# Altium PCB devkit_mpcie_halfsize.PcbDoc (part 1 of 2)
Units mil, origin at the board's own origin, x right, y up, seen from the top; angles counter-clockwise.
Board outline 1185.07 x 1313.97 mil, 4 copper layers (Top Layer, Mid-Layer 1, Mid-Layer 2, Bottom Layer), stack 34.6 mil thick; 83 components, 51 nets, 256 pads, 210 vias.
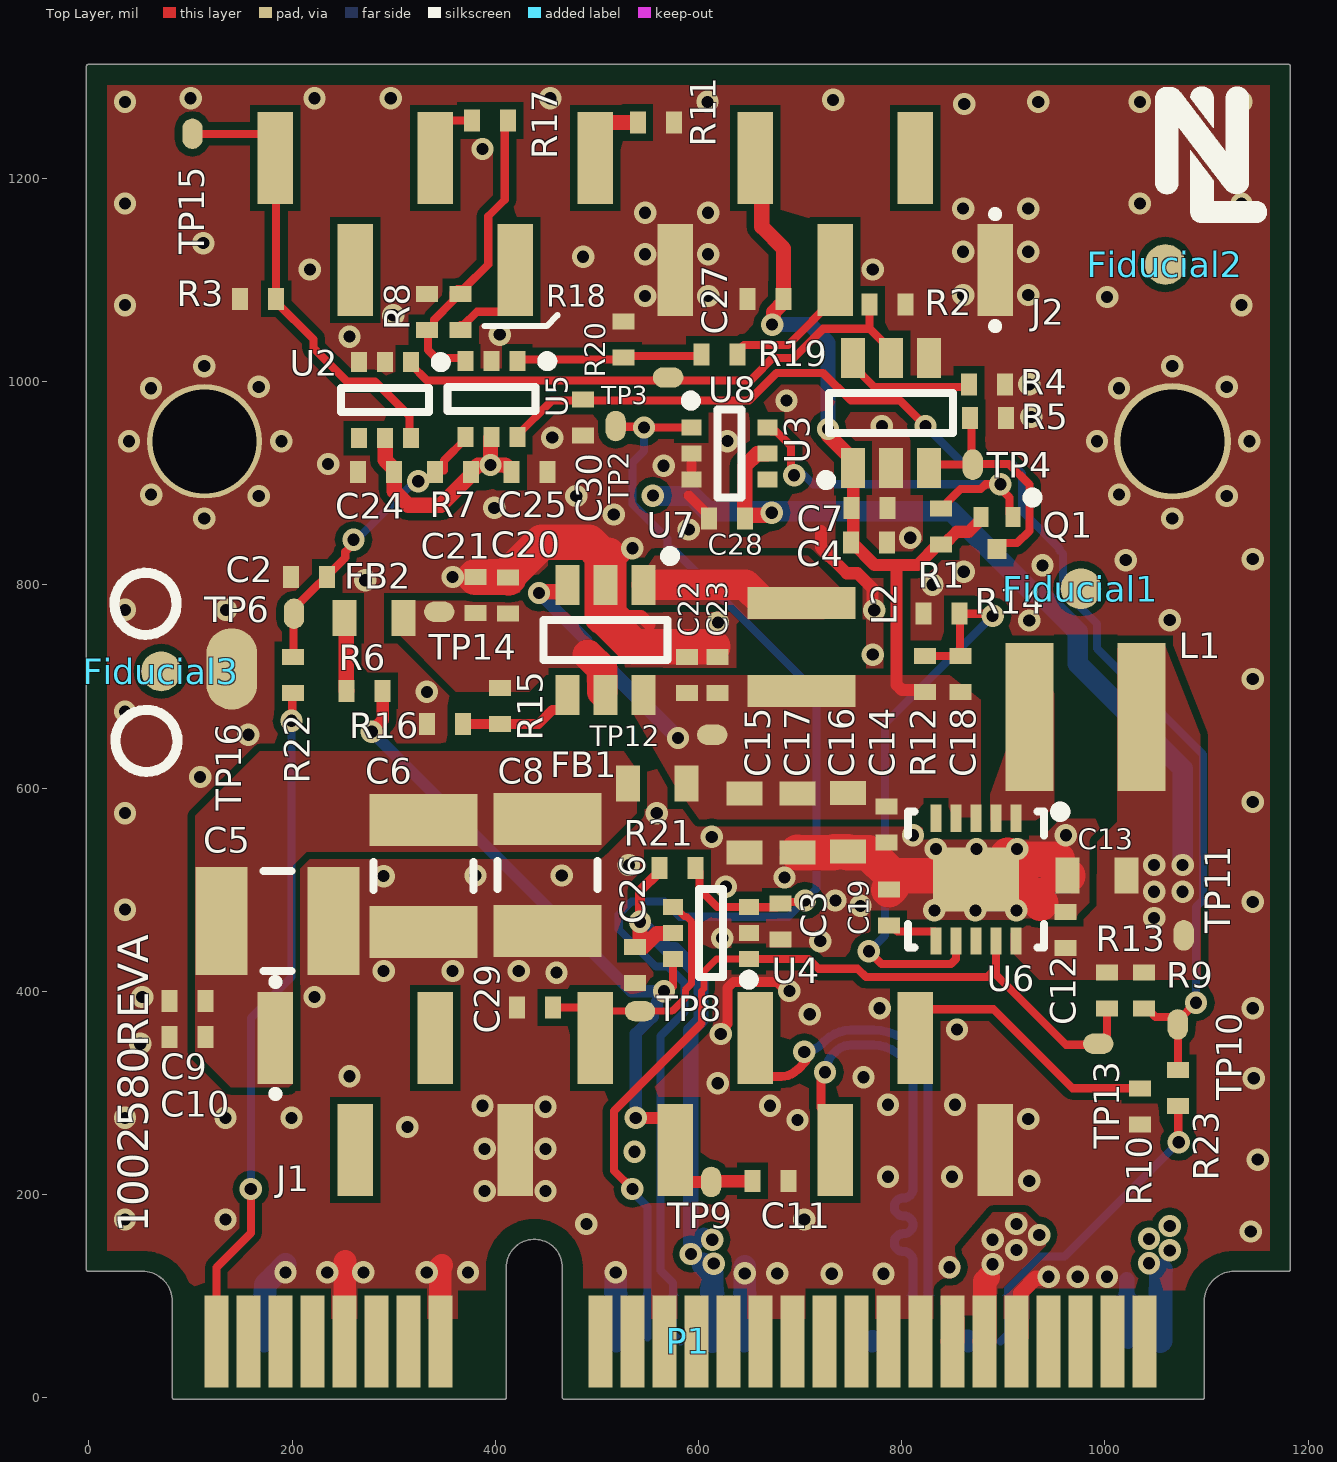
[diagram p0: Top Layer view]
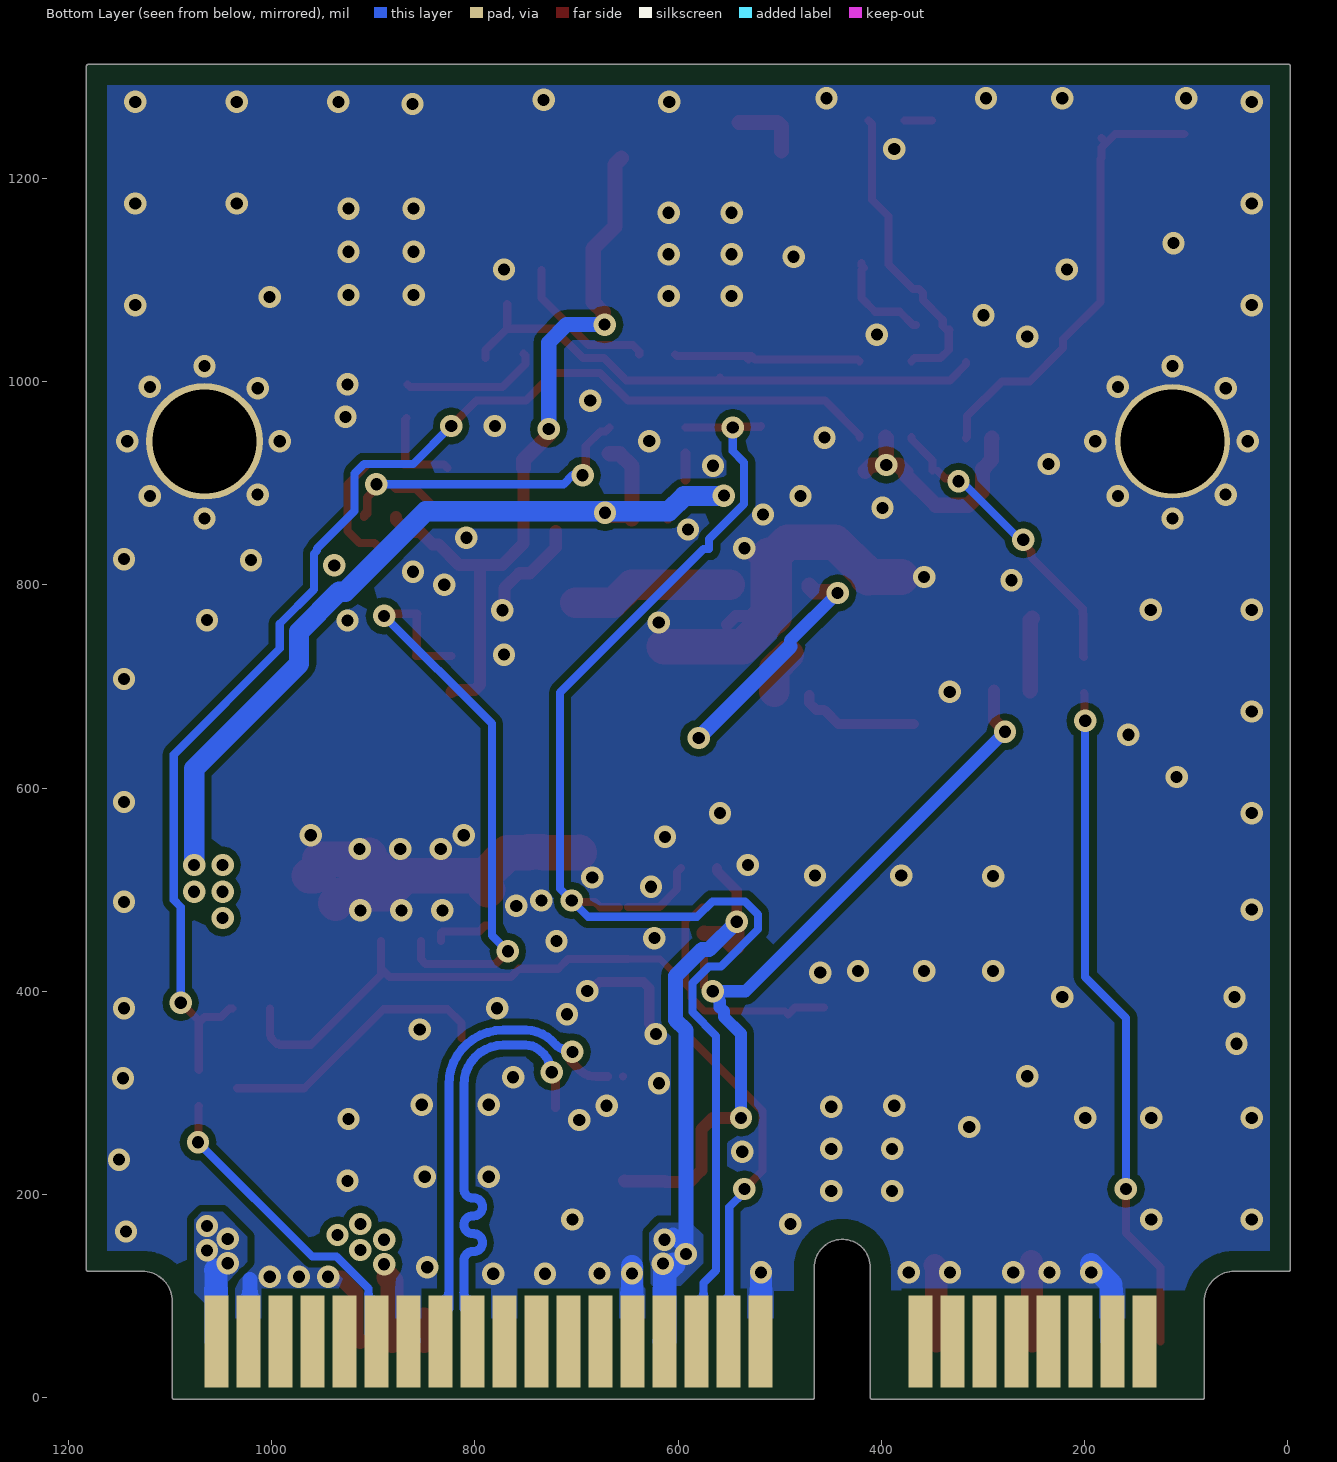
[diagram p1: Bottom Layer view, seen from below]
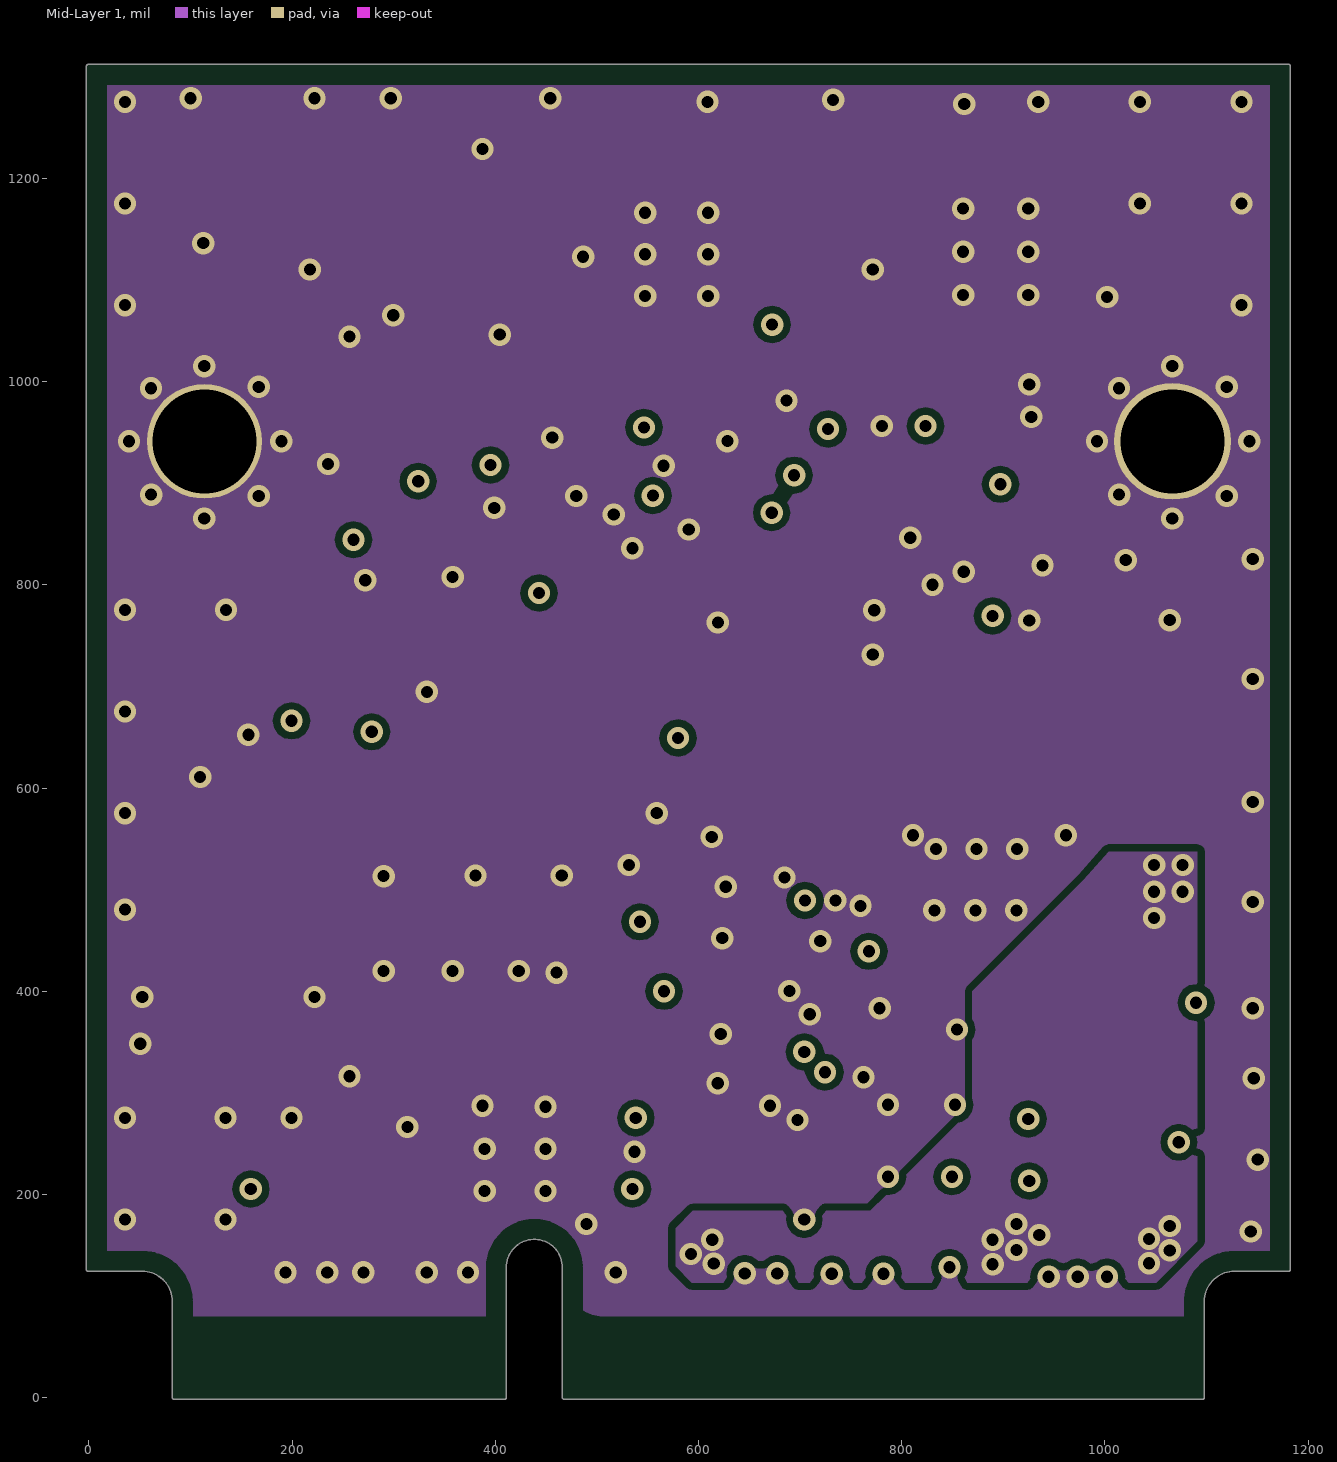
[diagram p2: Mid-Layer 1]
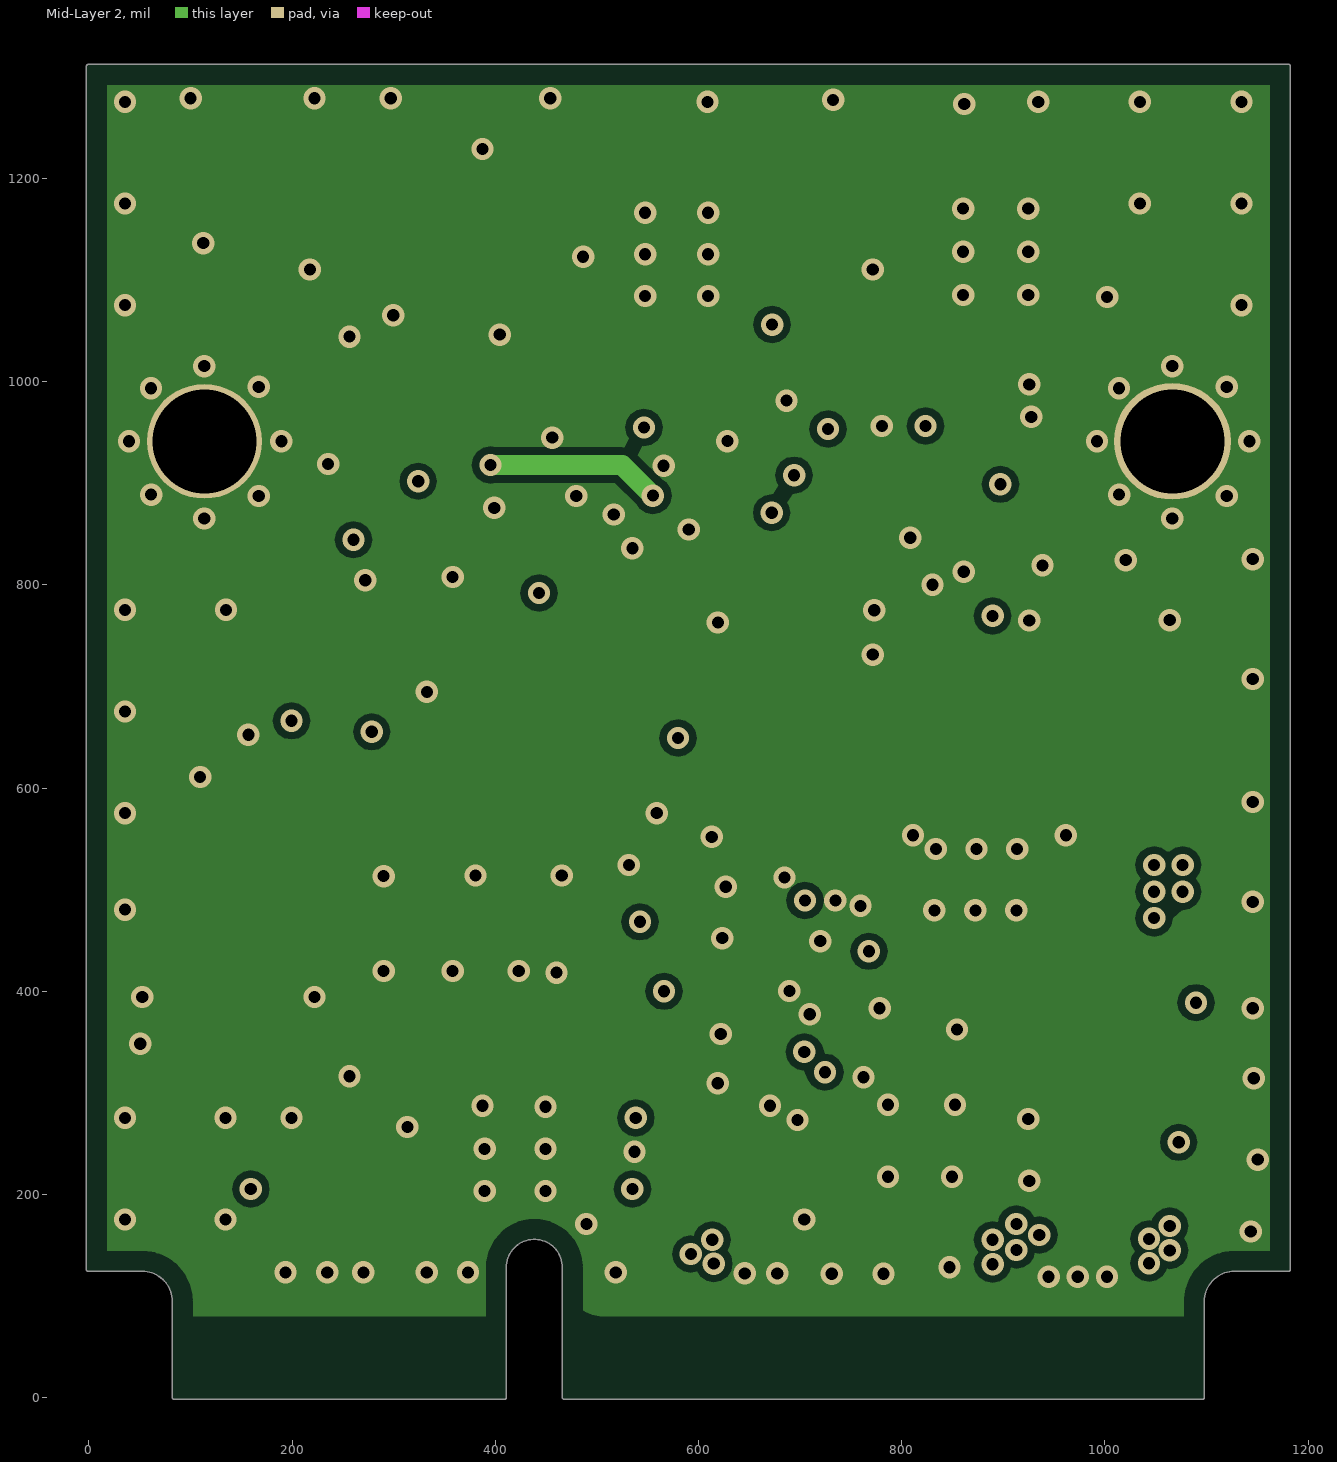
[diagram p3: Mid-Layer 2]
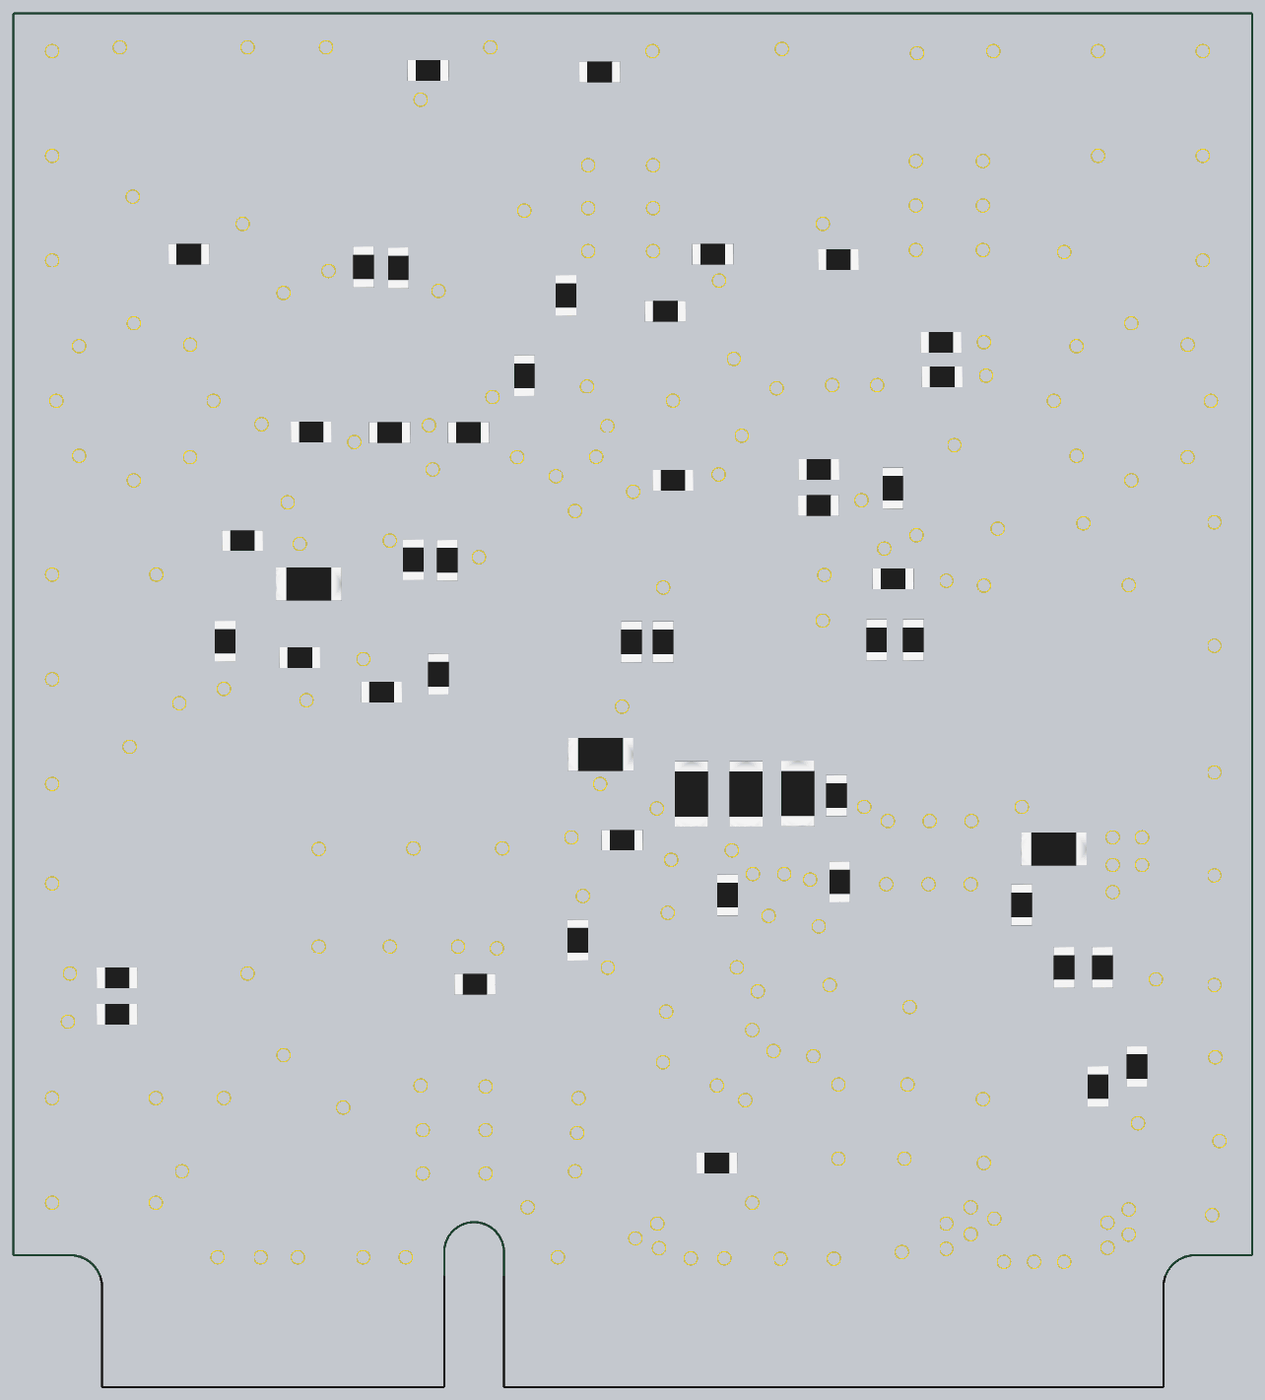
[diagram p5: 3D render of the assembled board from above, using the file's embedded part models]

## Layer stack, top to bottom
Top Solder: solder mask 1, Solder Resist, Dk 3.5
Top Layer: signal copper 0.6
Dielectric 1: dielectric 8, FR-4, Dk 4.5
Mid-Layer 1: signal copper 1.2
Dielectric2: dielectric 15, FR-4, Dk 4.5
Mid-Layer 2: signal copper 1.2
Dielectric3: dielectric 8, FR-4, Dk 4.5
Bottom Layer: signal copper 0.6
Bottom Solder: solder mask 1, Solder Resist, Dk 3.5

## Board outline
82.05,0.37 82.05,94.86 ccw(c52.54,94.86) 52.54,124.37 -0.61,124.37 cw(c-0.61,126.35) -2.6,126.35 -2.6,1310.37 cw(c-0.61,1310.37) -0.61,1312.35 1180.49,1312.35 cw(c1180.49,1310.37) 1182.47,1310.37 1182.47,126.35 cw(c1180.49,126.35) 1180.49,124.37 1127.34,124.37 ccw(c1127.34,94.86) 1097.83,94.86 1097.83,0.37 cw(c1095.84,0.37) 1095.84,-1.61 467.89,-1.61 cw(c467.89,0.37) 465.91,0.39 465.91,128.32 ccw(c438.36,128.32) 410.82,128.32 410.82,0.37 cw(c408.84,0.37) 408.84,-1.61 84.03,-1.61 cw(c84.03,0.37)

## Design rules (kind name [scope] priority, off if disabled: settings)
BoardOutlineClearance [All] p1: gap=10 ignorepadtopadclearanceinfootprint=FALSE except(0: Arc-SplitContinuation Track-SplitContinuation SMDPad-SplitContinuation THPad-SplitContinuation Via-SplitContinuation Fill-SplitContinuation Region-SplitContinuation Text-SplitContinuation; 20: Poly-OutlineEdge Poly-CavityEdge Poly-CutoutEdge Poly-SplitBarrior Poly-SplitContinuation)
Clearance "Pour Pullback" [InPoly vs OnLayer('Keep-Out Layer')] p1: gap=40 ignorepadtopadclearanceinfootprint=FALSE except(0: Arc-Hole Track-Hole SMDPad-Hole THPad-Hole Via-Hole Fill-Hole Poly-Hole Region-Hole Text-Hole)
Clearance "Polygon Clearance" [InPolygon] p2: gap=7 ignorepadtopadclearanceinfootprint=FALSE
Clearance "Trace and Space" [All] p3: gap=5 ignorepadtopadclearanceinfootprint=FALSE except(0: Arc-Hole Track-Hole SMDPad-Hole THPad-Hole Via-Hole Fill-Hole Poly-Hole Region-Hole Text-Hole)
ComponentClearance ComponentClearance_1 [Identifier='1002389_REVA_STEP'] p1: gap=0 collisioncheckmode=3 verticalgap=0 showdistances=FALSE
ComponentClearance [All] p2: gap=10 collisioncheckmode=3 verticalgap=10 showdistances=FALSE
DiffPairsRouting [All] p1: maxlimit=10 minlimit=6 mostfreqgap=6 toplayer_minwidth=7 toplayer_maxwidth=15 toplayer_prefwidth=8.8 midlayer1_minwidth=7 midlayer1_maxwidth=15 midlayer1_prefwidth=8.8 midlayer2_minwidth=7 midlayer2_maxwidth=15 midlayer2_prefwidth=8.8 bottomlayer_minwidth=7 bottomlayer_maxwidth=15 bottomlayer_prefwidth=8.8 maxuncoupledlength=500
HoleSize [All] p1: absolutevalues=TRUE maxlimit=10000 minlimit=10 maxpercent=80.000 minpercent=20.000
MinimumAnnularRing [All] p1: minimumring=5
MinimumSolderMaskSliver MinimumSolderMaskSliver_1 [InComponent('U6')] p1: minsoldermaskwidth=3
MinimumSolderMaskSliver [All] p2: minsoldermaskwidth=6
PlaneClearance [All] p1: clearance=10
PlaneConnect [All] p1: planeconnectstyle=Direct reliefexpansion=20 reliefentries=4 reliefconductorwidth=10 reliefairgap=10
PolygonConnect [All] p1: connectstyle=Direct reliefconductorwidth=10 reliefentries=4 polygonreliefangle="90 Angle" airgapwidth=10
RoutingVias [All] p1: holewidth=15 width=25 viastyle="Through Hole" minholewidth=10 minwidth=20 maxholewidth=400 maxwidth=500
SilkToSilkClearance [All] p1: silktosilkclearance=0
SilkToSolderMaskClearance [IsPad] p1: minsilkscreentomaskgap=1 clearancetoexposedcopper=TRUE
SolderMaskExpansion SolderMaskExpansion_1 [isVia] p1: expansion=-10
SolderMaskExpansion [All] p2: expansion=1
Width [All] p1: maxlimit=1000 minlimit=7 preferedwidth=8
22 further rules are at their usual default settings.

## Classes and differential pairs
component class "U_CON_PCI Express Mini_P1_52PIN": P1
component class TOP: C2 C3 C4 C5 C6 C7 C8 C9 C10 C11 C24 C25 C26 C27 C28 C29 C30 FB1 Fiducial1 Fiducial2 Fiducial3 J1 J2 PCB1 Q1 R1 R2 R3 R4 R5 R6 R7 R8 R9 R10 R11 R17 R18 R19 R20 R21 R22 R23 SCH1 TP2 TP3 TP4 TP6 TP8 TP9 TP10 TP15 TP16 U2 U3 U4 U5 U8
component class Power: C12 C13 C14 C15 C16 C17 C18 C19 C20 C21 C22 C23 FB2 L1 L2 R12 R13 R14 R15 R16 TP11 TP12 TP13 TP14 U6 U7
component class "Edge Connector": P1
differential pair SKY_USB: +SKY_USB_P -SKY_USB_N
differential pair REFCLK: +REFCLK_P -REFCLK_N
differential pair PET0: +PET0_P -PET0_N
differential pair PER0: +PER0_P -PER0_N

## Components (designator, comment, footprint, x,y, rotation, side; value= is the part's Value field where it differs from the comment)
C2 "CAPACITOR" 0402 217.21,807.8 r180 top
C3 "" 0402 680.39,469.37 r270 top
C4 "" 0402 767.37,841.37 r0 top
C5 "1001241" CAPC3225X25N_1210 185.39,469.37 r0 top
C6 "1001241" CAPC3225X25N_1210 329.36,513.37 r270 top
C7 "C, 33 pF, 50V, 5%, C0G/NP0, 0402 CER" 0402 767.71,875.62 r0 top
C8 "1001241" CAPC3225X25N_1210 451.39,514.37 r270 top
C9 "" 0402 97.39,390.37 r180 top
C10 "C, 33 pF, 50V, 5%, C0G/NP0, 0402 CER" 0402 97.39,355.37 r180 top
C11 "" 0402 670.36,213.37 r0 top
C12 "" 0402 961.53,460 r90 top
C13 "" 0603 992.14,513.91 r180 top
C14 "" 0402 784.65,564.45 r270 top
C15 "" 0603 645.39,565.62 r270 top
C16 "" 0603 747,566.37 r270 top
C17 "" 0603 697.39,565.62 r270 top
C18 "C, 18 pF, 50V, 5%, C0G/NPO, 0402 CER" 0402 857.79,712.86 r270 top
C19 "" 0402 787.39,481.84 r90 top
C20 "" 0402 412.61,789 r90 top
C21 "C, 10 uF, 10V, X5R, 20%, 0402 CER" 0402 380.4,789.62 r90 top
C22 "" 0402 588.66,711.01 r90 top
C23 "C, 10 uF, 10V, X5R, 20%, 0402 CER" 0402 618.89,711.01 r90 top
C24 "" 0402 282.85,911.46 r180 top
C25 "" 0402 433.15,910.93 r0 top
C26 "" 0402 537.39,426.22 r270 top
C27 "" 0402 666.39,1081.37 r180 top
C28 "" 0402 628.36,865.37 r180 top
C29 "CAPACITOR" 0402 439.29,384.11 r180 top
C30 "CAPACITOR" 0402 486.32,965.37 r270 top
FB1 "PE-0603PFB121ST" 0603 559.29,604.46 r180 top
FB2 "PE-0603PFB121ST" 0603 280.43,767.22 r180 top
Fiducial1 "Fiducial 1mm" "Fiducial 1mm"#1 976.39,796.3 r90 top
Fiducial2 "Fiducial 1mm" "Fiducial 1mm"#1 1059.39,1115.37 r90 top
Fiducial3 "Fiducial 1mm" "Fiducial 1mm"#2 71,715 r90 top
J1 "1000865" NPPN101BFLC-RC 183.44,354.08 r90 top locked
J2 "1000865" NPPN101BFLC-RC 891.93,1109.91 r270 top locked
L1 "INDUCTOR" MDWK4040 980.92,670 r180 top
L2 "INDUCTOR" NRS3015 701.22,739 r90 top
P1 "PCIeMini-CN-2S-M-R52" PCIeMini-GF-2D-800-1K-S52 589.94,55.49 r0 top locked
Q1 "MOSFET_P" SOT-723 893.58,851 r270 top
R1 "R, 10K, 1%, 1/16W,  0402" 0402 838.39,857.82 r270 top
R2 "R, 10K, 1%, 1/16W,  0402" 0402 786.39,1076.37 r180 top
R3 "RESISTOR" 0402 166.05,1081.35 r0 top
R4 "R, 10K, 1%, 1/16W,  0402" 0402 884.39,997.37 r180 top
R5 "R, 10K, 1%, 1/16W,  0402" 0402 885.39,964.37 r180 top
R6 "R, 1K, 1%, 1/16W, 0402" 0402 271.87,695.94 r180 top
R7 "R, 10K, 1%, 1/16W,  0402" 0402 357.87,910.93 r0 top
R8 "R, 10K, 1%, 1/16W,  0402" 0402 332.61,1069.29 r270 top
R9 "R, 10K, 1%, 1/16W,  0402" 0402 1038.76,400.23 r90 top
R10 "R, 1K, 1%, 1/16W, 0402" 0402 1034.39,286.37 r90 top
R11 "R, 1K, 1%, 1/16W, 0402" 0402 558.39,1255.37 r180 top
R12 "RESISTOR" 0402 822.82,712.86 r270 top
R13 "R, 100K, 1%, 1/16W,  0402" 0402 1002,400.23 r90 top
R14 "R, 100K, 1%, 1/16W,  0402" 0402 838.54,771.51 r0 top
R15 "R, 1M, 1%, 1/16W, 0402" 0402 404.48,680.31 r90 top
R16 "RESISTOR" 0402 350,663 r0 top
R17 "0" 0402 394.44,1257 r0 top
R18 "0" 0402 366,1068.37 r90 top
R19 "0" 0402 621,1027 r180 top
R20 "R, 10K, 1%, 1/16W,  0402" 0402 526,1042 r270 top
R21 "R, 10K, 1%, 1/16W,  0402" 0402 579.81,521.42 r180 top
R22 "0" 0402 200.54,711.75 r270 top
R23 "0" 0402 1071.62,305.37 r270 top
TP2 "Test Point 1mm" "Test_Point 1mm"#1 515.56,956.37 r90 top
TP3 "Test Point 1mm" "Test_Point 1mm"#2 558.81,993.56 r90 top
TP4 "Test Point 1mm" "Test_Point 1mm"#3 869.89,918.37 r270 top
TP6 "Test Point 1mm" "Test_Point 1mm"#3 201.82,771.66 r90 top
TP8 "Test Point 1mm" "Test_Point 1mm"#4 542.33,380.44 r90 top
TP9 "Test Point 1mm" "Test_Point 1mm"#3 612.39,212.37 r90 top
TP10 "Test Point 1mm" "Test_Point 1mm"#3 1071.62,367.37 r90 top
TP11 "Test Point 1mm" "Test_Point 1mm"#3 1077.5,455.03 r270 top
TP12 "Test Point 1mm" "Test_Point 1mm"#3 613.39,652.48 r180 top
TP13 "Test Point 1mm" "Test_Point 1mm"#3 993.39,348.37 r180 top
TP14 "Test Point 1mm" "Test_Point 1mm"#3 344.74,773.51 r180 top
TP15 "Test Point 1mm" "Test_Point 1mm"#3 101.83,1243.96 r90 top
TP16 "Test Point 1mm" "Test_Point 1mm"#5 140.54,717.25 r90 top
U2 "NL27WZ06DFT2G" SOT65P210X110-6N 291.14,981.78 r270 top
U3 "TPL5111" SOT95P280X110-6N 789.54,969.24 r90 top
U4 "NL27WZ07DFT2G" SOT65P210X110-6N 612.07,457.37 r180 top
U5 "NL27WZ06DFT2G" SOT65P210X110-6N 395.98,982.77 r270 top
U6 "TPS61230DRCR" PSON50P300X100_HS-11N 872.94,509.82 r270 top
U7 "TLV61220" SOT95P280X110-6N 508.37,745.81 r270 top
U8 "NL27WZ07DFT2G" SOT65P210X110-6N 630.32,929.37 r0 top

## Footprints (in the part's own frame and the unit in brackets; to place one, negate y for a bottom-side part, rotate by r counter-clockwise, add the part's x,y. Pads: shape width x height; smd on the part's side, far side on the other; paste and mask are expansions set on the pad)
0402 [mm]
  rect 0.4x0.55 smd: 1(-0.438,0.004) 2(0.462,0.004)
  body extent -0.5,-0.25 0.5,0.25, height 0.3
0603 [mm]
  rect 0.6x0.9 smd: 1(-0.737,0) 2(0.737,0)
  body extent -0.8,-0.38 0.8,0.42, height 0.45
CAPC3225X25N_1210 [mm] "Chip Capacitor, 2-Leads, 1210"
  rect 1.3x2.7 smd: 1(-1.4,0) 2(1.4,0)
  silkscreen extent -0.35,-1.25 0.35,1.25, body extent -1.7,-1.35 1.7,1.35, height 2.5
"Fiducial 1mm"#1 [mil]
  round 40 smd paste-19.68: Fiducial(0,0)
"Fiducial 1mm"#2 [mil]
  round 39.37 smd paste-19.68 mask+0: Fiducial(0,0)
MDWK4040 [mm] "Precision Wire Wound Inductor, 2-Leads, Body 4.00x4.00mm, IPC Medium Density"
  rect 1.2x3.7 smd: 1(-1.4,0) 2(1.4,0)
  body extent -2.1,-2.1 2.1,2.1, height 2
NPPN101BFLC-RC [mm] "Skywire Footprint with surfacemount pads"
  rect 2.29x0.89 smd: 1(0,0) 2(-2.8,-2) 3(0,-4) 4(-2.8,-6) 5(0,-8) 6(-2.8,-10) 7(0,-12) 8(-2.8,-14) 9(0,-16) 10(-2.8,-18)
  silkscreen extent -1.43,-0.03 1.43,0.03, body extent -3.54,-19.24 0.91,1.26, height 4.5
NRS3015 [mm] "Molded Inductor, 2-Leads, Body 3.00x3.00mm, IPC Medium Density"
  rect 0.8x2.7 smd: 1(-1.1,0) 2(1.1,0)
  body extent -1.55,-1.55 1.55,1.55, height 1.5
PCIeMini-GF-2D-800-1K-S52 [mm] "Golden finger, PCIeMini, Dual, Staggered, Pitch 0.8mm, 52-Position"
  rect 0.6x2.3 smd paste-0.9: 1(-11.8,0) 3(-11,0) 5(-10.2,0) 7(-9.4,0) 9(-8.6,0) 11(-7.8,0) 13(-7,0) 15(-6.2,0) 17(-2.2,0) 19(-1.4,0) 21(-0.6,0) 23(0.2,0) 25(1,0) 27(1.8,0) 29(2.6,0) 31(3.4,0) 33(4.2,0) 35(5,0) 37(5.8,0) 39(6.6,0) 41(7.4,0) 43(8.2,0) 45(9,0) 47(9.8,0) 49(10.6,0) 51(11.4,0)
  rect 0.6x2.3 smd far side paste-0.9: 2(-11.4,0) 4(-10.6,0) 6(-9.8,0) 8(-9,0) 10(-8.2,0) 12(-7.4,0) 14(-6.6,0) 16(-5.8,0) 18(-1.8,0) 20(-1,0) 22(-0.2,0) 24(0.6,0) 26(1.4,0) 28(2.2,0) 30(3,0) 32(3.8,0) 34(4.6,0) 36(5.4,0) 38(6.2,0) 40(7,0) 42(7.8,0) 44(8.6,0) 46(9.4,0) 48(10.2,0) 50(11,0) 52(11.8,0)
PSON50P300X100_HS-11N [mm] "PSON, 10-Leads, Body 3.00x3.00mm, Pitch 0.50mm, Thermal Pad 2.15x1.60mm, IPC Medium Density"
  rect 0.685x0.28 smd mask+0.07: 1(-1.532,1) 2(-1.532,0.5) 3(-1.532,0) 4(-1.532,-0.5) 5(-1.532,-1) 6(1.533,-1) 7(1.533,-0.5) 8(1.533,0) 9(1.533,0.5) 10(1.533,1)
  rect 1.6x2.15 smd paste-0.8 mask+0: 11(0,0)
  silkscreen extent -1.75,-1.7 1.7,2.09, body extent -1.55,-1.55 1.55,1.55, height 1
SOT65P210X110-6N [mm] "SOT23, 6-Leads, Body 2.00x2.10mm, Pitch 0.65mm, IPC Medium Density"
  rect 0.5x0.4 smd: 1(-0.95,0.65) 2(-0.95,0) 3(-0.95,-0.65) 4(0.95,-0.65) 5(0.95,0) 6(0.95,0.65)
  silkscreen extent -1.07,-1.1 0.3,1.53, body extent -0.67,-1.1 0.67,1.1, height 1.1
SOT95P280X110-6N [mm] "SOT23, 6-Leads, Body 2.90x2.80mm, Pitch 0.95mm, IPC Medium Density"
  rect 1x0.6 smd: 1(-1.375,0.95) 2(-1.375,0) 3(-1.375,-0.95) 4(1.375,-0.95) 5(1.375,0) 6(1.375,0.95)
  silkscreen extent -1.8,-1.55 0.5,1.75, body extent -0.88,-1.52 0.87,1.53, height 1.1
SOT-723 [mm]
  rect 0.5x0.37 smd: 1(-0.4,0.4) 2(-0.4,-0.4)
  rect 0.5x0.47 smd: 3(0.4,0)
  silkscreen extent -1.01,0.76 -0.76,1.01, body extent -0.45,-0.65 0.45,0.65, height 0.55
"Test_Point 1mm"#1 [mil]
  oval 30x20 smd paste-19.68 mask+0: 1(0,-2.83)
"Test_Point 1mm"#2 [mil]
  oval 20x30 smd paste-19.68 mask+0: 1(10.63,-11.19)
"Test_Point 1mm"#3 [mil]
  oval 30x20 smd paste-19.68 mask+0: 1(0,0)
"Test_Point 1mm"#4 [mil]
  oval 20x30 smd paste-19.68 mask+0: 1(0,0)
"Test_Point 1mm"#5 [mil]
  oval 80x50 smd paste-25 mask+0: 1(0,0)

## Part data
C2 C29 C30: library part 1000740, "Capacitor, 0.01 uF, 25V, 5%, X7R, 0402", Capacitance=0.01uF
C3 C4 C9 C11 C12 C14 C19 C20 C22 C24 C25 C26 C27 C28: library part 1000742, "Capacitor, 0.1 uF, 16V, 10%, X7R, 0402", Capacitance=0.10µF, Capacitor_Type=Ceramic, Manufacturer1=Kemet, Manufacturer2="Samsung Electro-Mechanics America, Inc", Manufacturer_Part_Number1=C0402C104K4RALTU, Manufacturer_Part_Number2=CL05B104KO5NNNC, Operating_Temperature="-55°C ~ 125°C", Package_Case="0402 (1005 Metric)", Temperature_Coefficient=X7R, Tolerance=±10%, Voltage_Rating=16V
C5 C6 C8: "Capacitor. 100uF, 10V, 20%, X5R, 1210", Capacitance=100uF, Capacitor_Type=Ceramic, Manufacturer1="Taiyo Yuden", Manufacturer_Part_Number1=LMK325BJ107MM-T, Operating_Temperature="-55C ~ +85C", Package_Case="1210 (3225 Metric)", Temperature_Coefficient=X5R, Tolerance="+/- 20%", Voltage_Rating=10V
C7 C10: library part 1000750, "Capacitor, 33 pF, 50V, 5%, C0G/NP0, 0402", Capacitance=33pF, Capacitor_Type=Ceramic, Manufacturer1=Kemet, Manufacturer_Part_Number1=C0402C330J5GACTU, Manufacturer_Part_Number2=C0402C330J5GACAUTO, Operating_Temperature="-55°C ~ 125°C", Package_Case="0402 (1005 Metric)", Temperature_Coefficient="C0G, NP0", Tolerance=±5%, Voltage_Rating=50V
C13 C15 C16 C17: library part 1000932, "Capacitor, 22 uF, 25V, 20%, X5R, 0603", Capacitance=22µF, Capacitor_Type=Ceramic, Manufacturer1="TDK Corporation", Manufacturer_Part_Number1=C1608X5R1A226M080AC, Operating_Temperature="-55°C ~ 85°C", Package_Case="0603 (1608 Metric)", Temperature_Coefficient=X5R, Tolerance=±20%, Voltage_Rating=10V
C18: library part 1000748, "Capacitor, 18 pF, 50V, 5%, C0G/NPO, 0402", Capacitance=18pF, Capacitor_Type=Ceramic, Manufacturer1="Samsung Electro-Mechanics America, Inc", Manufacturer_Part_Number1=CL05C180JB5NNNC, Operating_Temperature="-55°C ~ 125°C", Package_Case="0402 (1005 Metric)", Temperature_Coefficient="C0G, NP0", Tolerance=±5%, Voltage_Rating=50V
C21 C23: library part 1000737, "Capacitor, 10 uF, 10V, 20%, X5R, 0402", Capacitance=10µF, Capacitor_Type=Ceramic, Manufacturer1="Venkel LTD.", Manufacturer2="Samsung Electro-Mechanics America, Inc", Manufacturer_Part_Number1=C0402X5R100-106MNP, Manufacturer_Part_Number2=CL05A106MP8NUB8, Operating_Temperature="-55°C ~ 85°C", Package_Case="0402 (1005 Metric)", Temperature_Coefficient=X5R, Tolerance=±20%, Voltage_Rating=10V
FB1 FB2: library part 1000716, "Ferrite Bead, 120 ohm @100mHz, 2A, 50mOHM-DC, 0603", Manufacturer1="Murata Electronics North America", Manufacturer_Part_Number1=BLM18PG121SZ1D, Manufacturer_Part_Number2=BLM18PG121SH1D, Package_Case="0603 (1608 Metric)", Resistance_at_Frequency="120 @ 100MHz", Resistance_DC="50 mOhm"
Fiducial1 Fiducial2 Fiducial3: library part Fiducial
J1 J2: "Connector, Female, 2.00mm, 10x1, SMD, Left Oriented", Color=Black, Current_Rating=2A, Manufacturer1="Sullins Connector Solutions", Manufacturer_Part_Number1=NPPN101BFLC-RC, Operating_Temperature="-40°C ~ 105°C", Voltage_Rating=150V
L1: library part 1002223, "Inductor, 1 uH, 5.1A, 20%, 27 mOhm, Shielded, 4.00x4.00x2.00mm", Current_Rating=5.1A, Current_Saturation=7A, DC_Resistance="27 mOhm", Inductance="1.0 uH", Inductor_Type=Wirewound, Manufacturer1="Taiyo Yuden", Manufacturer_Part_Number1=MDWK4040T1R0MM, Operating_Temperature="-40C to +125C", Tolerance=20%
L2: library part 1002127, "Inductor, 4.7 uH, 1.04 A, 20%, 144 mOHM, Shielded, 3X3mm", Current_Rating=1.04A, Current_Saturation=1.02A, Inductance="4.7 uH", Inductor_Type=Wirewound, Manufacturer1="Taiyo Yuden", Manufacturer_Part_Number1=NRS3015T4R7MNGHV, Operating_Temperature="-40C to +125C", Package_Case=NR3015, Tolerance=20%
P1: library part CMP-0001-00067-2, "Golden finger, PCIeMini, Dual, Staggered, Pitch 0.8mm, 52-Position", Package Reference=PCIeMini-GF-2D-800-1K-S52, Package Version="rev1.2, Oct-2007"
Q1: library part 1001881, "Transistor, MOSFET, P-CH, 20V, 0.100A, SOT-723", Current_Continuous_Drain_at_25_deg_C="0.100 A", Drain_to_Source_Voltage=20V, Manufacturer1="Rohm Semiconductor", Manufacturer_Part_Number1=RZM001P02T2L, Operating_Temperature="-55°C ~ 150°C", Package_Case=SOT-723
R1 R2 R4 R5 R7 R8 R9 R20 R21: library part 1000795, "Resistor, 10K, 1%, 1/16W, 0402", Manufacturer1="Bourns Inc", Manufacturer_Part_Number1=CR0402-FX-1002GLF, Manufacturer_Part_Number2=CR0402-FX-1002GAS, Operating_Temperature="-55°C ~ 155°C", Power="0.063W, 1/16W", Resistance_Ohms=10k, Resistor_Package="0402 (1005 Metric)", Temperature_Coefficient=±100ppm/°C, Tolerance=±1%
R3: library part 1001865, "Resistor, 0, 1/16W, 0402", Manufacturer1="Bourns Inc", Manufacturer2="Samsung Electro-Mechanics America, Inc", Manufacturer_Part_Number1=CR0402-J/-000GLF, Manufacturer_Part_Number2=RCS1005J000CS, Operating_Temperature="-55C ~ 155C", Power=1/16W, Resistance_Ohms=0, Resistor_Package="0402 (1005 Metric)"
R6 R10 R11: library part 1000794, "Resistor, 1K, 1%, 1/16W, 0402", Manufacturer1="Bourns Inc", Manufacturer2="Samsung Electro-Mechanics America, Inc", Manufacturer_Part_Number1=CR0402-FX-1001GLF, Manufacturer_Part_Number2=RC1005F102CS, Operating_Temperature="-55°C ~ 155°C", Power="0.063W, 1/16W", Resistance_Ohms=1k, Resistor_Package="0402 (1005 Metric)", Temperature_Coefficient=±100ppm/°C, Tolerance=±1%
R12: library part 1002126, "Resistor, 300K, 1%, 1/16W, 0402", Manufacturer1="Stackpole Electronics Inc", Manufacturer2=Yageo, Manufacturer_Part_Number1=RMCF0402FT300k, Manufacturer_Part_Number2=RC0402FR-07300KL, Operating_Temperature="-55C to 155C", Power=1/16W, Resistance_Ohms=300k, Resistor_Package="0402 (1005 Metric)", Temperature_Coefficient=±100ppm/°C, Tolerance=1%
R13 R14: library part 1000796, "Resistor, 100K, 1%, 1/16W, 0402", Manufacturer1="Bourns Inc", Manufacturer2="Samsung Electro-Mechanics America, Inc", Manufacturer_Part_Number1=CR0402-FX-1003GLF, Manufacturer_Part_Number2=RC1005F104CS, Operating_Temperature="-55°C ~ 155°C", Power="0.063W, 1/16W", Resistance_Ohms=100k, Resistor_Package="0402 (1005 Metric)", Temperature_Coefficient=±100ppm/°C, Tolerance=±1%
R15: library part 1000797, "Resistor, 1M, 1%, 1/16W, 0402", Manufacturer1="Bourns Inc", Manufacturer2="Samsung Electro-Mechanics America, Inc", Manufacturer_Part_Number1=CR0402-FX-1004GLF, Manufacturer_Part_Number2=RC1005F105CS, Operating_Temperature="-55°C ~ 155°C", Power="0.063W, 1/16W", Resistance_Ohms=1M, Resistor_Package="0402 (1005 Metric)", Temperature_Coefficient=±100ppm/°C, Tolerance=±1%
R16: library part 1002128, "Resistor, 110K, 1%, 1/16W, 0402", Manufacturer1=Yageo, Manufacturer_Part_Number1=RC0402FR-07110KL, Operating_Temperature="-55C to +125C", Power=1/16W, Resistance_Ohms=110K, Resistor_Package="0402 (1005 Metric)", Temperature_Coefficient=±100ppm/°C, Tolerance=1%
R17 R18 R19 R22 R23: library part 1000574, "Resistor, 0, 1/10W, 0402", Manufacturer1="Panasonic Electronic Components", Manufacturer_Part_Number1=ERJ-2GE0R00X, Operating_Temperature="-55°C ~ 155°C", Power="0.1W, 1/10W", Resistor_Package="0402 (1005 Metric)", Temperature_Coefficient=-, Tolerance=Jumper
TP2 TP3 TP4 TP6 TP8 TP9 TP10 TP11 TP12 TP13 TP14 TP15 TP16: library part TP_1mm, "TEST POINT, SMD 1mm"
U2 U5: library part 1000524, "IC, Inverter, Dual, Open Drain,1.65-5.5V, SC88", Manufacturer1="ON Semiconductor", Operating_Temperature="-55°C ~ 125°C", Package_Case="6-TSSOP, SC-88, SOT-363", Voltage_Supply_Max=5.5V, Voltage_Supply_Min=1.65V, Voltage_Supply_Typical=-
U3: library part 1002129, "IC, Timer, 0.1-7200s, 1%, 1.8V-5.5V, TSOT-23-6", Manufacturer1="Texas Instruments", Manufacturer_Part_Number1=TPL5111DDCR, Operating_Temperature="-40C to +105C", Package_Case=TSOT-23-6, Voltage_Supply_Max=5.5V, Voltage_Supply_Min=1.8V, Voltage_Supply_Typical=3.3V
U4 U8: library part 1001575, "IC, Buffer, Dual, Open Drain,1.65-5.5V, SC88", Manufacturer1="ON Semiconductor", Operating_Temperature="-55°C ~ 125°C", Package_Case="6-TSSOP, SC-88, SOT-363", Voltage_Supply_Max=5.5V, Voltage_Supply_Min=1.65V, Voltage_Supply_Typical=-
U6: library part 1001034, "IC, Boost, ADJ, 2.5V-5.5V, 2.1A, VSON", Manufacturer1="Texas Instruments", Operating_Temperature="-40°C ~ 125°C", Package_Case="10-VFDFN Exposed Pad", Voltage_Supply_Typical=-
U7: library part 1002116, "IC, BOOST, ADJ, 1.8V-5.5V, 0.22A, SOT-23-6", Manufacturer1="Texas Instruments", Manufacturer_Part_Number1=TLV61220DBVR, Operating_Temperature="-40C to +85C", Package_Case=SOT-23-6, Voltage_Supply_Max=5.5V, Voltage_Supply_Min=0.7V, Voltage_Supply_Typical=3.3

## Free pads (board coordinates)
  oval 20x60 on Mech15: 1(183.44,354.08) 2(891.93,1116.91)
  round 200 on Top Solder: 3(1066.32,941.32) 4(113.56,941.32)
  round 113 hole 102.36: MH1(113.56,941.32)
  round 115 hole 102.36: MH2(1066.32,941.32)

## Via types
v1: diameter 22, hole 12, Top Layer to Bottom Layer, 210 vias

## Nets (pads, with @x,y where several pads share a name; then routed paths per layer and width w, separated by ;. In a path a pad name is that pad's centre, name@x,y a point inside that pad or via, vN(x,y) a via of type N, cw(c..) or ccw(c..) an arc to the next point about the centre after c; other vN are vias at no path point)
CLKREQ#: P1.7
COEX1: P1.3
COEX2: P1.5
GND: C2.2 C3.2 C4.2 C5.2 C6.2 C7.2 C8.2 C9.2 C10.2 C11.2 C12.2 C13.2 C14.2 C15.2 C16.2 C17.2 C19.2 C20.2 C21.2 C22.2 C23.2 C24.2 C25.2 C26.2 C27.2 C28.2 C29.2 C30.2 J1.4 J1.10 J2.1 J2.5 P1.4 P1.9 P1.15 P1.18 P1.21 P1.26 P1.27 P1.29 P1.34 P1.35 P1.37 P1.40 P1.43 P1.50 pad.MH1 pad.MH2 R2.1 R3.1 R4.1 R5.1 R8.1 R10.1 R11.1 R14.1 R16.1 R20.1 TP16.1 U2.2 U2.3 U3.2 U3.4 U4.2 U5.2 U6.11 U7.2 U8.2 U8.3 | length 1658.8
  Top Layer w10: 590.35,888 610.19,868.17 C28.2@610.19,865.22 ; U8.3@592.91,903.78 U8.2@592.91,929.37 ; v1(621.88,358) 621.88,361.25 628.36,367.73 628.36,403.3 634.22,409.16 677.54,409.16 686.46,400.23 v1(689.4,400.23)
  Top Layer w12: U7.2@511,810.45 522.96,822.41 ; v1@534.82,836.05 522.96,824.19 522.96,822.41 ; 551.78,760.86 543.38,769.26 529.4,769.26 522.96,775.7 522.96,822.41 ; 720.5,852.93 720.5,836.88 745.84,811.54 756.44,811.54 771.04,796.95 771.04,776.91 v1(772.95,774.99)
  Top Layer w15: P1.43@912.77,55.49 917.09,59.8 917.09,103.07 931.65,117.64 943.17,117.64 v1(944.51,118.97)
  Top Layer w22: P1.9@251.36,55.49 251.78,55.91 251.78,133.76 252.39,134.37 ; P1.15@345.84,55.49 345.84,128.83 347.39,130.37
  Top Layer w35: C21.2@380.25,807.8 410.51,807.8 C20.2@411.17,808.46 ; C20.2@411.51,808.8 416.5,813.79 417.42,813.79 445.75,842.13 492.1,842.13 505.28,828.95 505.28,768.86 506.59,768.86 536.46,739 613.79,739 ; C20.2@412.46,807.18 C20.2@413.13,807.18 ; U7.2@511,810.45 511,828.95 ; C17.2@697.39,536.62 697.51,536.5 732.62,536.5 733.49,537.37 C16.2@747,537.37 ; C16.2@747,536.5 767.6,536.5 790.19,513.91 ; C19.2@787.24,500.01 790.19,502.96 790.19,513.91 ; U6.11@904.1,534.05 U6.11@904.1,530.15 ; 936.92,486.84 927.93,495.83 886.94,495.83 U6.11@872.94,509.82 ; C13.2@963.14,513.91 957.67,513.91 952.77,518.82 952.77,530.15 U6.11@904.1,530.15 ; 790.19,513.91 868.86,513.91 U6.11@872.94,509.82 ; U6.11@872.94,509.82 883.77,509.82 U6.11@904.1,530.15
  Bottom Layer w15: 1021.39,116.37 1021.39,57.11 P1.50@1023.01,55.49
  Bottom Layer w22: P1.4@172.62,55.49 173.43,56.3 173.43,111.28 181.89,119.74 181.89,119.87 v1@193.39,131.37 ; v1(518.39,123.37) 518.39,56.17 P1.18@519.07,55.49 ; P1.26@645.06,55.49 645.39,55.82 v1(645.39,122.37) v1@645.39,129.37 ; P1.34@771.04,55.49 P1.34@771.39,55.84 ; P1.40@864.72,56.3 P1.40@865.53,55.49
  other v1: 973.25,118.97 1002,118.97 677.39,122.37 731,121.93 782,121.93 193.39,123.37 234.47,123.37 270.11,123.37 332.39,123.37 373.07,123.37 847,128.32 1143.39,163.64 489.56,171 35.39,175.37 134.39,175.37 704.07,175.37 389.39,203.37 449.39,203.37 925.39,213.37 786.39,217.45 849.39,217.45 1150.39,234.37 536.86,242 389.39,244.87 449.39,244.87 313.39,266.37 697.39,273.37 924.39,274.37 35.39,275.37 134.39,275.37 199.39,275.37 449.39,286.37 387.32,287.37 670.36,287.37 786.39,288.37 852.39,288.37 618.86,309.54 1146.39,314.37 762.39,315.37 256.39,316.37 50.39,348.37 854.39,362.37 709.39,377.37 778.15,383.37 1145.39,383.37 52.39,394.37 222,394.37 460.11,418.41 290,420 357.87,420 423,420 719.76,449.42 623.39,452.37 35.39,480.37 832.06,479.63 872.42,479.63 912.77,479.63 759.37,484.06 1145.39,488 734.62,489.37 626.69,502.96 684.58,512 290,513.37 380.4,513.91 465.33,513.91 531.39,524.37 833.57,540 873.55,540 913.53,540 613,552 810.99,553.53 961.53,553.53 35.39,575.37 558.81,575.37 1145.39,586.37 109.39,610.92 156.87,652.48 35.39,675.37 332.61,694.69 1145.39,707.37 771.46,731.36 619,763 925.39,764.89 1063.69,765.32 35.39,775.37 134.89,775.37 830.21,800.12 271.87,804.66 357.87,807.8 861,813 938.5,819.21 1020.39,824.37 1145.39,825.36 534.82,836.1 808.39,846.37 590.35,854.52 113.39,865.37 1066.14,865.37 516.47,869.31 398.85,875.77 167.14,887.49 479.52,887.49 1119.9,887.49 61.12,888.86 1013.87,888.86 565.62,917.2 235.39,919 39.39,941.31 189.39,941.31 992.14,941.31 1142.14,941.31 628.36,941.55 456,945 780.39,956.37 927.39,965.37 686.46,981.37 61.07,993.56 1013.83,993.56 167.18,994.93 1119.94,994.93 925.39,997.37 113.39,1015.37 1066.14,1015.37 256.39,1044.37 404.39,1046.37 299.39,1065.37 35.39,1075.37 1134.39,1075.37 1002.09,1083.41 547.39,1084.37 609.39,1084.37 860.39,1085.37 924.39,1085.37 217.39,1110.37 771.46,1110.37 486.32,1123 547.39,1125.37 609.39,1125.37 860.39,1127.87 924.39,1127.87 112.39,1136.37 547.39,1166.37 609.39,1166.37 860.39,1170.37 924.39,1170.37 35.39,1175.37 1034.39,1175.37 1134.39,1175.37 387.32,1229 861.51,1273.37 35.39,1275.37 608.79,1275.37 934.39,1275.37 1034.39,1275.37 1134.39,1275.37 732.39,1277.37 100,1279 222,1279 297,1279 454,1279
LED: P1.42 R23.2 | length 318.7
  Top Layer w8: R23.2@1071.78,287.2 1072.16,286.81 1072.16,251.76 v1(1072.55,251.37)
  Bottom Layer w8: P1.42@897.03,55.49 904.84,63.3 904.84,107.59 936.22,138.97 960.15,138.97 v1(1072.55,251.37)
LED_WLAN#: P1.44
LED_WPAN#: P1.46
M_DRV: Q1.3 R5.2 TP4.1 U3.3 | length 241
  Top Layer w8: U3.3@826.94,915.1 830.21,918.37 TP4.1@869.89,918.37 ; R5.2@867.21,964.22 868.55,962.88 868.55,919.71 TP4.1@869.89,918.37 ; Q1.3@893.58,835.25 893.58,835.84 898.83,841.09 913.53,841.09 925.61,853.18 925.61,898.7 905.31,919 870.52,919 TP4.1@869.89,918.37
NetC2_1: C2.1 R7.1 R22.1 TP6.1 U5.4 | length 300.6
  Top Layer w8: R22.1@200.7,729 201.26,729.56 201.26,771.1 TP6.1@201.82,771.66 201.82,776.66 252.29,827.14 252.29,832.59 260.34,840.63 v1(260.34,844.42) v1@257.66,841.74 ; 252.65,828.8 252.65,831.75 ; v1(324,902) 326.68,904.68 337.11,904.68 R7.1@344.48,912.05 ; 349.46,912.43 349.46,922.48 370.39,943.4 U5.4@370.39,945.37
  Bottom Layer w8: v1(260.34,844.42) 263.38,844.42 320.96,902 v1(324,902)
NetC5_1: C5.1 C6.1 C8.1 C9.1 C10.1 FB1.2 J1.1
NetC18_1: C18.1 R12.1 R14.2 U6.7 | length 601.7
  Top Layer w8: v1(767.6,439.34) 779.94,427.01 848.57,427.01 853.26,431.7 U6.7@853.26,449.49 ; R12.1@822.97,730.12 C18.1@857.95,730.12 857.33,730.73 857.33,771.05 R14.2@856.72,771.66 887.24,771.66 v1(889.39,769.51)
  Bottom Layer w8: v1(767.6,439.34) 783.36,455.09 783.36,663.48 v1(889.39,769.51)
NetC19_1: C19.1 U6.6 | length 57.3
  Top Layer w8: C19.1@787.24,464.58 790.19,464.58 795.8,458.97 832.06,458.97 833.57,457.46 U6.6@833.57,449.49
NetC20_1: C20.1 C21.1 FB2.1 R15.2 TP14.1 U7.5 | length 42.3
  Top Layer w30: 491.06,731.36 505.18,717.25 U7.5@505.18,694.87
NetC29_1: C29.1 J1.5 TP8.1 U4.4 | length 242
  Top Layer w7: J1.5@491.64,377.2 494.88,380.44 TP8.1@542.33,380.44 574.02,380.44 587.17,393.59 587.17,401.55 593.01,407.39 593.01,468.77 588.03,473.74 585.85,473.74 576.64,482.96 U4.4@574.67,482.96
  Top Layer w8: C29.1@456.54,383.96 484.88,383.96 J1.5@491.64,377.2
NetC30_1: C30.1 R9.1 R23.1 TP10.1 U5.6 | length 1277.4
  Top Layer w8: U5.6@421.57,945.37 421.57,947.34 455.6,981.37 649.44,981.37 676.72,1008.64 722.64,1008.64 749.92,981.37 798.39,981.37 v1(823.39,956.37) ; R9.1@1038.6,382.98 1041.56,382.98 1049.87,374.67 1066.08,374.67 1071.62,369.12 TP10.1@1071.62,367.37 ; R23.1@1071.78,322.63 1071.78,370.99 v1(1089.6,388.82) v1@1088.84,388.82
  Bottom Layer w8: v1(823.39,956.37) 860.76,919 909,919 918.5,909.5 918.5,872.71 955.32,835.89 955.32,833.86 958.5,830.68 958.5,795.42 992.14,761.78 992.14,737.29 1096.39,633.04 1096.39,489.72 1089.6,482.93 v1(1089.6,388.82)
NetJ1_9: J1.9 R10.2 | length 273.5
  Top Layer w8: J1.9@813.36,354.08 813.36,368.85 826.88,382.37 890.17,382.37 967.99,304.55 R10.2@1034.23,304.55
NetJ2_3: J2.3 R19.1 | length 148.5
  Top Layer w8: R19.1@638.26,1026.85 638.26,1029.8 644.65,1036.19 688.28,1036.19 734.45,1082.35 J2.3@734.45,1109.91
